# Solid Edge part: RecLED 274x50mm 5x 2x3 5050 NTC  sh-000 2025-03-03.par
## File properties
Author: patryk.ciesielski
Template: iso metric part.par
Last saved by: patryk.ciesielski
Revision: 1
Application: Solid Edge
Gęstość: 0,000 kg/m^3
Dokładność: 0,990
Username: patryk.ciesielski
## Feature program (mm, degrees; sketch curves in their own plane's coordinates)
body "unnamed Body 1"
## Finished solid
Body 1: solid body, 1154 faces, 2923 edges, 1858 vertices.
  Faces by surface: plane 623, cylinder 264, torus 104, cone 88, spline 53, sphere 20, swept 2
  Edges by curve: line 1612, curve on surface 695, circle 276, spline 208, ellipse 132
Bounding box of the edges (mm; curved faces can reach further): 49.500 x 273.800 x 4.950, from (-24.75, -136.9, -1.5) to (24.75, 136.9, 3.45).
Cylindrical faces by radius (mm): R0.199 x2, R0.2 x78, R0.2002 x4, R0.2169 x6, R0.25 x24, R0.3 x4, R0.3373 x6, R0.4 x16, R0.4006 x4, R0.4008 x4, R0.525 x4, R0.6 x24, R1 x14, R1.05 x10, R1.0894 x4, R1.0991 x8, R1.1 x28, R1.5273 x4, R1.5275 x4, R1.7415 x1, R1.75 x5, R3.8655 x1, R5.0788 x1, R5.4676 x1, R5.8707 x1, R6.0498 x1, R7.7441 x1, R7.8435 x1, R7.9901 x1, R10.0612 x1, R12.8203 x1
Conical faces (half-angle, radius in mm at the cone's reference point): 0.3913 deg R1.0968 x4, 0.447 deg R1.0952 x4, 0.464 deg R1.0955 x4, 0.5 deg R0.5056 x8, 0.5 deg R1.0082 x8, 1 deg R0.5511 x4, 10 deg R0.2132 x4, 10 deg R0.4132 x4, 15.6748 deg R1.1041 x2, 15.6751 deg R1.1041 x2, 15.7937 deg R1.1267 x2, 15.7938 deg R1.1267 x2, 18.4844 deg R1.0657 x8, 18.9316 deg R0.5099 x4, 19.4337 deg R0.5111 x4, 27.363 deg R0.6214 x4, 40.1968 deg R0.519 x2, 40.228 deg R0.5176 x2, 42.9179 deg R0.4919 x2, 42.9331 deg R0.4916 x2, 45 deg R0.575 x4, 45 deg R0.625 x8
Toroidal faces (ring radius, tube radius in mm): R0.0958 r0.3997 x8, R0.1 r0.2 x2, R0.1075 r0.4 x4, R0.1101 r0.4001 x4, R0.1216 r0.4 x4, R0.1234 r0.4 x4, R0.1634 r0.2287 x2, R0.1641 r0.2287 x2, R0.3286 r0.2001 x2, R0.3702 r0.4 x4, R0.3818 r0.2 x4, R0.4163 r0.3984 x4, R0.4824 r0.2001 x2, R0.4952 r0.2 x2, R0.6008 r0.3968 x4, R0.6009 r0.3969 x4, R0.6227 r0.2 x2, R0.6235 r0.2 x2, R0.8 r0.2 x8, R0.8522 r0.3 x4, R0.9002 r0.2 x2, R0.9018 r0.2 x2, R0.9181 r0.2227 x4, R0.9197 r0.223 x2, R0.9199 r0.223 x2, R0.9663 r0.2263 x2, R0.9665 r0.2263 x2, R1.3 r0.2 x4, R1.327 r1.1 x4, R1.3271 r1.1 x4, R1.8741 r0.2175 x2, R1.8987 r0.2 x2
Spherical faces by radius (mm): R0.2 x16, R0.6 x4
Planar faces by outward normal: +x 67, +y 67, +z 115, -x 67, -y 86, -z 15, oblique 206
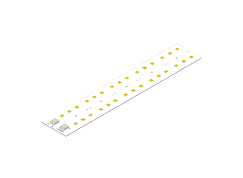
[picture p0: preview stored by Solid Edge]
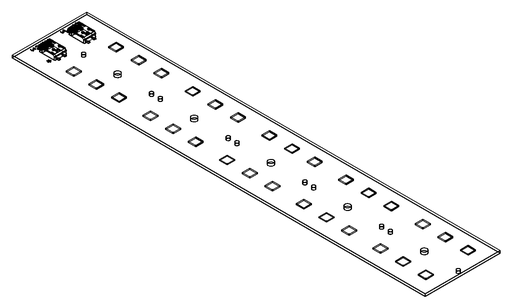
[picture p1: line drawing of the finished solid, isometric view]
